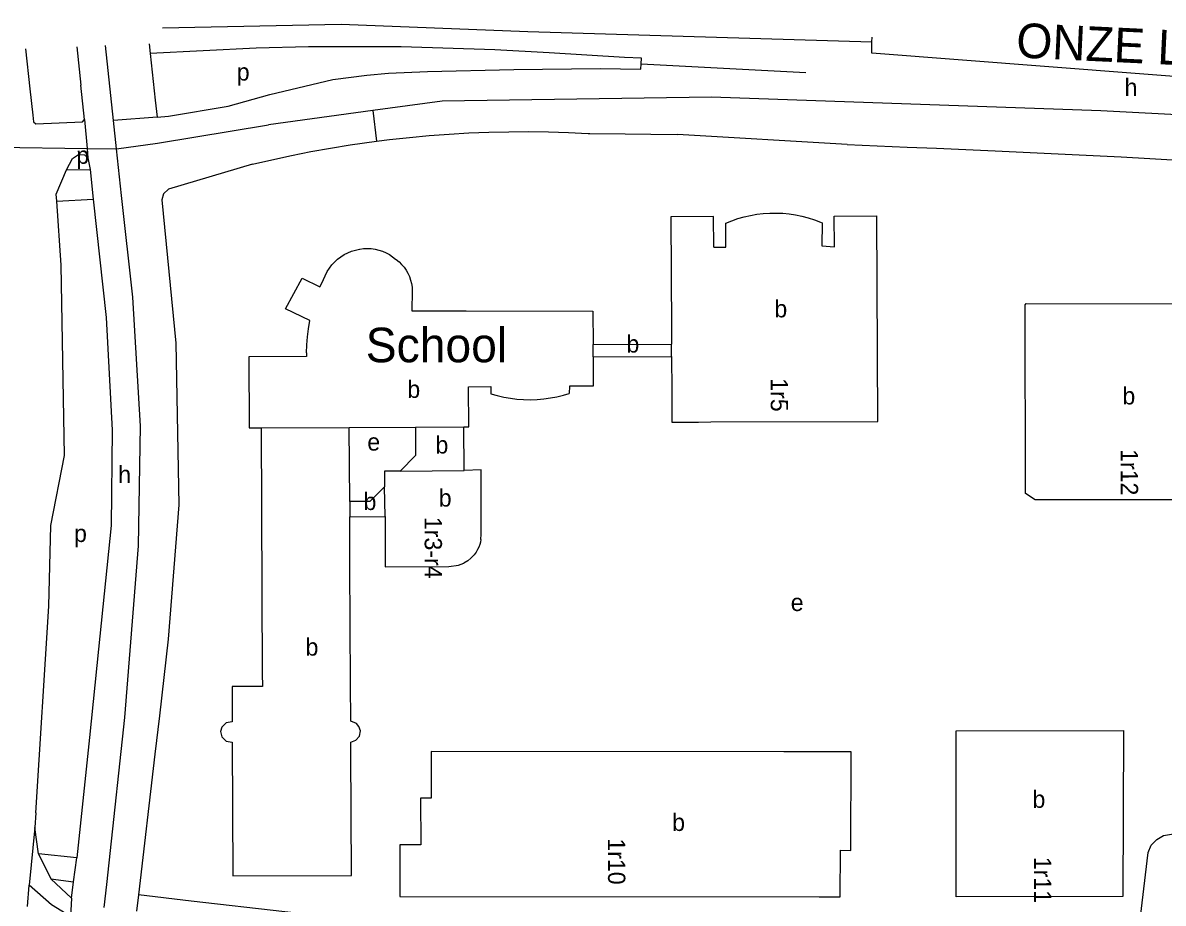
# Model space of a CAD drawing. Extents: x 159902 to 161769, y 383692 to 384875.
# Drawn here: x 161286.9 to 161550.6, y 384671.8 to 384875.4 of the extents above; entities that cross this region are included whole.
import ezdxf

# ---------------------------------------------------------------- set-up
doc = ezdxf.new("R2010")
doc.units = 0
for name, color, linetype in [('BLT_Basislijn', 7, 'Continuous'), ('BLT_Bebouwing', 7, 'Continuous'), ('BLT_Bebouwing_beschrifting', 7, 'Continuous'), ('BLT_Centroide', 7, 'Continuous'), ('BLT_Huisnummer', 7, 'Continuous'), ('BLT_Huisnummer_reeks', 7, 'Continuous'), ('BLT_Onderdoorgang_en_onderverdeling', 7, 'Continuous'), ('BLT_Onderverdeling_panden', 7, 'Continuous'), ('BLT_Straatnaam_hoofdweg', 7, 'Continuous'), ('BLT_Vlakafsluiter', 7, 'Continuous')]:
    doc.layers.add(name, color=color, linetype=linetype)

msp = doc.modelspace()

# ---------------------------------------------------------------- linework, layer by layer
at = {"layer": 'BLT_Basislijn'}
for p, q in [((161316.12, 384870.58), (161316.36, 384868.34)), ((161287.58, 384869.4), (161288.57, 384860.18)), ((161299.39, 384869.9), (161300.36, 384860.98)), ((161429.82, 384864.7), (161429.9, 384865.94)), ((161429.9, 384865.94), (161429.99, 384867.21)), ((161429.9, 384865.94), (161467.97, 384863.96)), ((161367.86, 384855.12), (161368.73, 384848.05)), ((161317.98, 384853.63), (161307.9, 384852.85)), ((161418.02, 384849.81), (161426.22, 384849.72)), ((161426.22, 384849.72), (161432.19, 384849.65)), ((161432.19, 384849.65), (161438.33, 384849.58)), ((161477.59, 384847.29), (161438.33, 384849.58)), ((161477.59, 384847.29), (161491.41, 384846.65)), ((161491.41, 384846.65), (161498.25, 384846.4)), ((161306.91, 384681.17), (161310.53, 384714.76)), ((161317.46, 384706.28), (161313.65, 384673.74)), ((161289.92, 384692.74), (161289.71, 384689.31)), ((161299.43, 384682.35), (161290.6, 384683.27)), ((161298.67, 384676.74), (161299.43, 384682.35)), ((161306.37, 384676.16), (161306.91, 384681.17)), ((161288.01, 384671.1), (161288.4, 384675.98)), ((161293.38, 384677.45), (161298.67, 384676.74)), ((161293.38, 384677.45), (161298.16, 384672.97)), ((161305.73, 384670.82), (161306.37, 384676.16)), ((161313.65, 384673.74), (161313.21, 384669.96)), ((161325.83, 384672.33), (161313.65, 384673.74)), ((161369.21, 384667.33), (161325.83, 384672.33))]:
    msp.add_line(p, q, dxfattribs=at)
for points in [[(161319.22, 384874.29), (161360.55, 384875.1), (161403.74, 384873.43), (161483.29, 384871.04)], [(161565.09, 384862.1), (161483.25, 384868.44), (161483.29, 384871.04)], [(161483.29, 384871.04), (161483.31, 384872.07)], [(161307.9, 384852.85), (161306.03, 384870.14)], [(161429.99, 384867.21), (161426.06, 384867.43), (161408.67, 384868.51), (161396.11, 384869.19), (161374.43, 384869.85), (161353.01, 384869.83), (161340.87, 384869.57), (161316.36, 384868.34)], [(161316.36, 384868.34), (161317.53, 384857.52), (161317.98, 384853.63)], [(161317.98, 384853.63), (161320.62, 384853.86), (161334.44, 384856.14), (161344.03, 384858.88), (161358.6, 384862.33), (161366.52, 384863.33), (161371.48, 384863.79), (161380.49, 384864.14), (161400.46, 384864.63), (161420.47, 384864.87), (161429.82, 384864.7)], [(161288.57, 384860.18), (161289.23, 384854.08), (161289.4, 384852.53), (161289.95, 384852.04), (161300.74, 384852.54), (161301.23, 384853.07)], [(161301.23, 384853.07), (161300.36, 384860.98)], [(161446.16, 384858.25), (161383.91, 384857.33), (161367.86, 384855.12)], [(161659.78, 384846.77), (161619.39, 384849.53), (161581.77, 384852.64), (161536.21, 384855.06), (161446.16, 384858.25)], [(161367.86, 384855.12), (161343.73, 384851.8)], [(161308.62, 384846.26), (161318.06, 384847.58), (161343.73, 384851.8)], [(161371.74, 384848.43), (161376.32, 384848.93), (161380.9, 384849.35), (161385.5, 384849.69), (161390.09, 384849.95), (161394.69, 384850.13), (161399.29, 384850.23), (161403.9, 384850.25), (161408.5, 384850.19), (161413.1, 384850.05), (161417.7, 384849.83), (161418.02, 384849.81)], [(161340.05, 384842.72), (161344.53, 384843.77), (161349.03, 384844.75), (161353.55, 384845.64), (161358.08, 384846.46), (161362.62, 384847.19), (161368.73, 384848.05)], [(161368.73, 384848.05), (161371.74, 384848.43)], [(161297.07, 384841.45), (161298.44, 384844.08), (161299.82, 384844.97), (161301.19, 384844.88), (161301.99, 384844.17)], [(161301.99, 384844.17), (161302.48, 384841.51)], [(161310.53, 384714.76), (161313.7, 384754.46), (161314.15, 384782.11), (161312.35, 384812.01), (161309.77, 384835.49), (161308.62, 384846.26)], [(161498.25, 384846.4), (161511.76, 384845.81), (161526.33, 384845.16), (161540.89, 384844.43), (161555.46, 384843.61), (161570.01, 384842.72), (161584.56, 384841.75), (161599.11, 384840.7), (161613.65, 384839.57), (161628.18, 384838.36), (161628.32, 384838.35)], [(161294.77, 384834.14), (161294.67, 384835.8), (161297.07, 384841.45)], [(161297.07, 384841.45), (161302.48, 384841.51)], [(161302.48, 384841.51), (161303.22, 384834.64)], [(161340.05, 384842.72), (161320.65, 384836.95), (161319.44, 384835.87), (161319.11, 384834.5), (161322.32, 384801.34), (161323.01, 384763.93), (161320.57, 384732.92), (161318.54, 384715.18)], [(161292.95, 384740.55), (161293.4, 384759.19), (161296.55, 384775.35), (161295.79, 384819.37), (161294.77, 384834.14)], [(161294.77, 384834.14), (161303.22, 384834.64)], [(161303.22, 384834.64), (161306.22, 384807.27), (161307.6, 384781.19), (161307.33, 384759.17), (161304.44, 384730.54)], [(161289.92, 384692.74), (161292.95, 384740.55)], [(161304.44, 384730.54), (161302.32, 384710.17), (161299.43, 384682.35)], [(161318.54, 384715.18), (161317.46, 384706.28)], [(161290.6, 384683.27), (161289.71, 384689.31)], [(161541.46, 384646.31), (161543.88, 384666.77), (161545.4, 384668.68), (161547.18, 384683.52), (161547.86, 384685.23), (161549.17, 384686.54), (161550.74, 384687.5), (161552.57, 384687.8), (161556.63, 384687.87)], [(161290.6, 384683.27), (161293.38, 384677.45)], [(161297.98, 384668.73), (161293.54, 384671.48), (161288.4, 384675.98)], [(161298.16, 384672.97), (161298.67, 384676.74)]]:
    msp.add_lwpolyline(points, dxfattribs=at)
at = {"layer": 'BLT_Bebouwing'}
for p, q in [((161436.81, 384830.55), (161436.93, 384804.45)), ((161378.74, 384808.85), (161389.44, 384808.82)), ((161436.93, 384804.45), (161436.92, 384801.1)), ((161418.81, 384801.04), (161436.92, 384801.1)), ((161418.82, 384798.21), (161436.94, 384798.25)), ((161436.94, 384798.25), (161436.99, 384790.42)), ((161443.18, 384783.09), (161446.06, 384783.11)), ((161370.71, 384761.23), (161370.75, 384749.62)), ((161362.94, 384678.24), (161362.8, 384707.01))]:
    msp.add_line(p, q, dxfattribs=at)
for points in [[(161449.48, 384829.09), (161450.87, 384829.65), (161452.29, 384830.14), (161453.74, 384830.55), (161455.2, 384830.89), (161456.68, 384831.14), (161458.17, 384831.32), (161459.66, 384831.42), (161461.16, 384831.43), (161462.66, 384831.37), (161464.16, 384831.23), (161465.64, 384831.01), (161467.11, 384830.71), (161468.56, 384830.33), (161469.99, 384829.87), (161471.4, 384829.34), (161471.76, 384829.19)], [(161471.76, 384829.19), (161471.68, 384823.85), (161474.62, 384823.61), (161474.57, 384830.72), (161484.44, 384830.78)], [(161484.65, 384783.26), (161484.44, 384830.78)], [(161446.72, 384823.51), (161446.68, 384830.61), (161436.81, 384830.55)], [(161446.72, 384823.51), (161449.53, 384823.52), (161449.48, 384829.09)], [(161357.32, 384817.91), (161357.83, 384818.7), (161358.41, 384819.43), (161359.05, 384820.12), (161359.74, 384820.74), (161360.49, 384821.31), (161361.28, 384821.81), (161362.11, 384822.24), (161362.97, 384822.6), (161363.87, 384822.88), (161364.78, 384823.09), (161364.85, 384823.1)], [(161364.85, 384823.1), (161365.73, 384823.21), (161366.62, 384823.25), (161367.51, 384823.2), (161368.4, 384823.08), (161369.26, 384822.88), (161370.11, 384822.6), (161370.93, 384822.24), (161371.71, 384821.82), (161372.45, 384821.32), (161373.14, 384820.76), (161373.26, 384820.65)], [(161373.26, 384820.65), (161373.93, 384820.13), (161374.54, 384819.55), (161375.09, 384818.92), (161375.57, 384818.23), (161375.99, 384817.5), (161376.35, 384816.74), (161376.62, 384815.94), (161376.82, 384815.12), (161376.94, 384814.29), (161376.98, 384813.45), (161376.98, 384813.41)], [(161352.52, 384799.1), (161352.6, 384800.95), (161352.76, 384802.79), (161352.99, 384804.62), (161353.3, 384806.59), (161347.7, 384809.31), (161351.5, 384816.36), (161355.59, 384814.35), (161356.05, 384815.25), (161356.82, 384816.93), (161357.32, 384817.91)], [(161376.98, 384813.41), (161376.92, 384808.85), (161378.74, 384808.85)], [(161389.44, 384808.82), (161418.77, 384808.75), (161418.81, 384801.04)], [(161352.52, 384799.1), (161352.55, 384798.26), (161339.2, 384798.18), (161339.27, 384781.75)], [(161418.82, 384798.21), (161418.86, 384791.41), (161413.33, 384791.37), (161413.31, 384789.72)], [(161388.92, 384781.98), (161390.11, 384781.98), (161390.02, 384791.27), (161395.14, 384791.3), (161395.15, 384789.64)], [(161395.15, 384789.64), (161396.64, 384789.21), (161398.15, 384788.87), (161399.67, 384788.6), (161401.21, 384788.41), (161402.75, 384788.3), (161404.3, 384788.27), (161405.84, 384788.32), (161407.39, 384788.45), (161408.92, 384788.66), (161410.44, 384788.95), (161411.94, 384789.31), (161413.31, 384789.72)], [(161436.99, 384790.42), (161437.02, 384783.07), (161443.18, 384783.09)], [(161446.06, 384783.11), (161484.65, 384783.26)], [(161339.27, 384781.75), (161342.08, 384781.76)], [(161342.08, 384781.76), (161342.32, 384724.98)], [(161362.43, 384781.84), (161377.73, 384781.91)], [(161362.52, 384764.69), (161362.43, 384781.84)], [(161377.73, 384781.91), (161377.76, 384775.33)], [(161389, 384771.91), (161388.92, 384781.98)], [(161377.76, 384775.33), (161374.21, 384771.75)], [(161374.21, 384771.75), (161370.6, 384771.77), (161370.58, 384768.11)], [(161392.87, 384755.95), (161392.95, 384757.16), (161392.89, 384772.02), (161389, 384771.91)], [(161370.58, 384768.11), (161367.21, 384764.71), (161362.52, 384764.69)], [(161362.53, 384761.19), (161370.71, 384761.23)], [(161362.59, 384750), (161362.53, 384761.19)], [(161392.87, 384755.95), (161392.75, 384755.34), (161392.58, 384754.75), (161392.37, 384754.19), (161392.1, 384753.62), (161391.75, 384753.04), (161391.27, 384752.35), (161390.57, 384751.62), (161389.83, 384751), (161388.9, 384750.46)], [(161362.72, 384722.57), (161362.59, 384750)], [(161370.75, 384749.62), (161385.47, 384749.68), (161387.72, 384750), (161388.9, 384750.46)], [(161342.32, 384724.98), (161342.33, 384721.94), (161335.34, 384721.92), (161335.37, 384713.79), (161333.94, 384713.55), (161332.92, 384712.53), (161332.65, 384711.53), (161332.92, 384710.31), (161333.96, 384709.3), (161335.38, 384709.08), (161335.48, 384678.13)], [(161362.8, 384707.01), (161362.79, 384709.06), (161363.97, 384709.49), (161364.77, 384710.46), (161364.99, 384711.7), (161364.67, 384712.7), (161364.12, 384713.35), (161362.77, 384713.9), (161362.72, 384722.57)], [(161335.48, 384678.13), (161362.94, 384678.24)]]:
    msp.add_lwpolyline(points, dxfattribs=at)
for points in [[(161518.72, 384810.21), (161518.99, 384810.48), (161562.6, 384810.45), (161562.87, 384810.18), (161562.92, 384766.54), (161560.65, 384765.12), (161521.03, 384765.14), (161518.77, 384766.57)], [(161502.73, 384711.72), (161541.45, 384711.77), (161541.32, 384673.39), (161502.79, 384673.33)], [(161471.07, 384673.33), (161475.97, 384673.33), (161475.98, 384684.07), (161478.38, 384684.05), (161478.49, 384706.82), (161462.92, 384706.82), (161381.34, 384706.87), (161381.34, 384696.09), (161378.93, 384696.09), (161378.94, 384685.29), (161374.13, 384685.29), (161374.13, 384673.35)]]:
    msp.add_lwpolyline(points, close=True, dxfattribs=at)
at = {"layer": 'BLT_Onderdoorgang_en_onderverdeling'}
for p, q in [((161418.82, 384798.21), (161418.81, 384801.04)), ((161436.94, 384798.25), (161436.92, 384801.1))]:
    msp.add_line(p, q, dxfattribs=at)
at = {"layer": 'BLT_Onderverdeling_panden'}
for p, q in [((161342.08, 384781.76), (161362.43, 384781.84)), ((161377.73, 384781.91), (161388.92, 384781.98)), ((161374.21, 384771.75), (161389, 384771.91)), ((161370.71, 384761.23), (161370.58, 384768.11)), ((161362.52, 384764.69), (161362.53, 384761.19))]:
    msp.add_line(p, q, dxfattribs=at)
at = {"layer": 'BLT_Vlakafsluiter'}
for p, q in [((161301.23, 384853.07), (161301.8, 384846.33)), ((161308.62, 384846.26), (161307.9, 384852.85)), ((161279.14, 384846.73), (161301.8, 384846.33)), ((161301.8, 384846.33), (161301.99, 384844.17)), ((161301.8, 384846.33), (161308.62, 384846.26)), ((161289.71, 384689.31), (161288.4, 384675.98)), ((161298.16, 384672.97), (161297.98, 384668.73))]:
    msp.add_line(p, q, dxfattribs=at)

# ---------------------------------------------------------------- texts
at = {"layer": 'BLT_Bebouwing_beschrifting'}
msp.add_text('School', height=8, dxfattribs=at).set_placement((161366.23, 384796.92))
at = {"layer": 'BLT_Centroide'}
for s, p in [('p', (161336.41, 384862.06)), ('h', (161541.7, 384858.51)), ('p', (161299.3, 384842.81)), ('b', (161460.73, 384807.3)), ('b', (161426.52, 384799.16)), ('b', (161375.85, 384788.68)), ('b', (161541.21, 384787.16)), ('e', (161366.6, 384776.49)), ('b', (161382.36, 384775.82)), ('h', (161308.99, 384768.98)), ('b', (161383.12, 384763.55)), ('b', (161365.72, 384762.75)), ('p', (161298.78, 384755.35)), ('e', (161464.51, 384739.39)), ('b', (161352.31, 384729.08)), ('b', (161520.41, 384693.87)), ('b', (161437.09, 384688.53))]:
    msp.add_text(s, height=4, dxfattribs=at).set_placement(p)
at = {"layer": 'BLT_Huisnummer'}
for s, p in [('1r5', (161459.87, 384793.22)), ('1r12', (161540.81, 384776.84)), ('1r10', (161422.23, 384686.82)), ('1r11', (161520.77, 384682.55))]:
    msp.add_text(s, height=4, rotation=270.1784, dxfattribs=at).set_placement(p)
at = {"layer": 'BLT_Huisnummer_reeks'}
msp.add_text('1r3-r4', height=4, rotation=270.1784, dxfattribs=at).set_placement((161379.84, 384761.16))
at = {"layer": 'BLT_Straatnaam_hoofdweg'}
msp.add_text('ONZE LIEVE VROUWESTRAAT', height=7.9999, rotation=357.276, dxfattribs=at).set_placement((161516.53, 384867.43))

doc.saveas('drawing.dxf')
